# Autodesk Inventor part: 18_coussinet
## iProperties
Created: 2002-11
Part Number: 18_coussinet
Material: Laiton (jaune doux)
Document SubType Name: Modélisation
Designer: poste-2
Control State: 0
Master: False
Checked Out: False
Shininess: 20.0
Length Units: 11269
Angle Units: 11279
Time Units: 11290
Mass Units: 11283
Length Display Precision: 3
Angle Display Precision: 2
Compacted: True
Density: 8.47
Volumn: 1.8306322191855517
Area: 16.4643855650485
PropertySet Name: Model Information
Author: poste-2
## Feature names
1. Révolution1 [Revolution]
